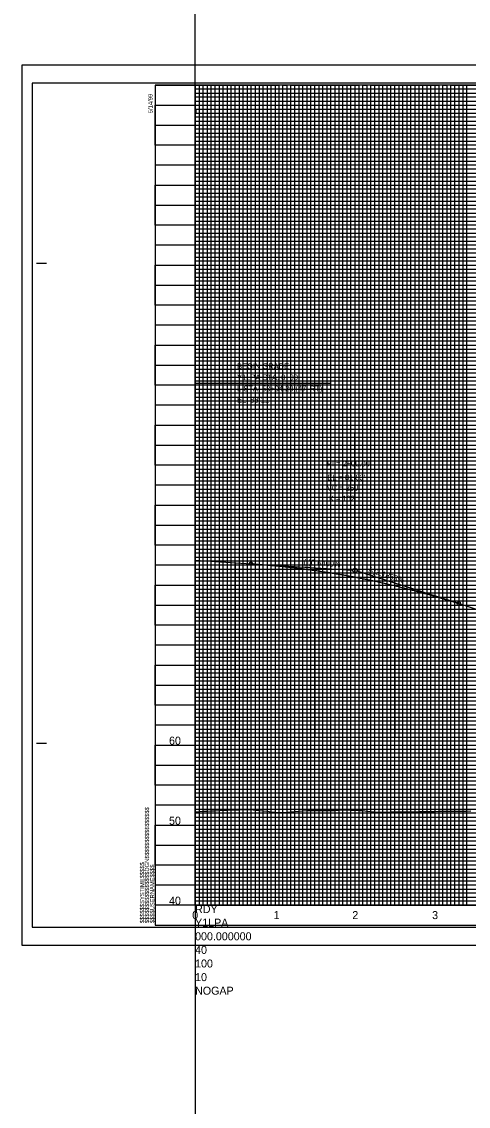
# Model space of a CAD drawing. Extents: x 2345490 to 2436403, y 465165 to 573888.
# Drawn here: x 2410678 to 2411237, y 518231 to 519587 of the extents above; entities that cross this region are included whole.
import ezdxf

# ---------------------------------------------------------------- set-up
doc = ezdxf.new("R2010")
doc.units = 0
for name, color, linetype in [('Old_Level_1', 7, 'Continuous'), ('Old_Level_18', 7, 'Continuous'), ('Old_Level_2', 7, 'Continuous'), ('Old_Level_40', 7, 'Continuous'), ('Old_Level_41', 7, 'Continuous'), ('Old_Level_42', 7, 'Continuous'), ('Old_Level_43', 7, 'Continuous'), ('Old_Level_50', 7, 'Continuous'), ('Old_Level_51', 7, 'Continuous'), ('Old_Level_52', 7, 'Continuous'), ('Old_Level_63', 7, 'Continuous')]:
    doc.layers.add(name, color=color, linetype=linetype)

msp = doc.modelspace()

# ---------------------------------------------------------------- linework, layer by layer
at = {"layer": 'Old_Level_1'}
msp.add_lwpolyline([(2410895.325, 518599.101), (2410900.325, 518599.36625), (2410905.325, 518599.6315), (2410910.325, 518599.897), (2410915.325, 518600.16275), (2410920.325, 518600.42875), (2410925.325, 518600.701), (2410930.325, 518600.896), (2410935.325, 518601.09075), (2410940.325, 518601.286), (2410945.325, 518601.4815), (2410950.325, 518601.677), (2410955.325, 518601.873), (2410960.325, 518602.069), (2410965.325, 518601.73975), (2410970.325, 518601.21325), (2410975.325, 518600.688), (2410980.325, 518600.164), (2410985.325, 518599.64175), (2410990.325, 518599.12075), (2410995.325, 518598.60025), (2411000.325, 518598.07125), (2411005.325, 518598.2125), (2411010.325, 518598.5945), (2411015.325, 518598.98175), (2411020.325, 518599.3745), (2411025.325, 518599.773), (2411030.325, 518600.1775), (2411035.325, 518600.58825), (2411040.325, 518600.65375), (2411045.325, 518600.54725), (2411050.325, 518600.59475), (2411055.325, 518600.6425), (2411060.325, 518600.69075), (2411065.325, 518600.73925), (2411070.325, 518600.78825), (2411075.325, 518601.0075), (2411080.325, 518601.3745), (2411085.325, 518601.44475), (2411090.325, 518601.18475), (2411095.325, 518600.93), (2411100.325, 518600.6805), (2411105.325, 518600.4365), (2411110.325, 518599.981), (2411115.325, 518599.5135), (2411120.325, 518599.05), (2411125.325, 518598.6505), (2411130.325, 518598.69575), (2411135.325, 518598.74275), (2411140.325, 518598.79175), (2411145.325, 518598.84275), (2411150.325, 518598.89575), (2411155.325, 518598.9505), (2411160.325, 518599.0075), (2411165.325, 518599.08675), (2411170.325, 518599.092), (2411175.325, 518599.186), (2411180.325, 518599.2755), (2411185.325, 518599.3645), (2411190.325, 518599.453), (2411195.325, 518599.54075), (2411200.325, 518599.628), (2411205.325, 518599.71475), (2411210.325, 518599.80075), (2411215.325, 518599.886), (2411220.325, 518599.8485), (2411225.325, 518599.77525), (2411230.325, 518599.77475), (2411235.325, 518599.83525), (2411240.325, 518600.069)], dxfattribs=at)
at = {"layer": 'Old_Level_18'}
msp.add_line((2410845.325, 518457.40475), (2410845.325, 518457.40475), dxfattribs=at)
msp.add_line((2410845.325, 518457.40475), (2410845.325, 518457.40475), dxfattribs=at)
msp.add_lwpolyline([(2412345.325, 519507.40475), (2410845.325, 519507.40475), (2410845.325, 518457.40475), (2412345.325, 518457.40475)], close=True, dxfattribs=at)
at = {"layer": 'Old_Level_2'}
for p, q in [((2410895.325, 519134.40475), (2410895.325, 518913.50475)), ((2411063.7915, 519134.40475), (2410895.325, 519134.40475)), ((2410895.325, 518913.50475), (2410965.325, 518909.02475)), ((2410965.325, 518909.02475), (2411092.58075, 518900.88075)), ((2411225.325, 518859.28375), (2411097.94525, 518899.87025)), ((2411225.325, 518859.28375), (2411745.325, 518693.59875))]:
    msp.add_line(p, q, dxfattribs=at)
for centre, radius in [((2410965.325, 518909.02475), 2.25), ((2411095.325, 518900.705), 2.75), ((2411225.325, 518859.28375), 2.25)]:
    msp.add_circle(centre, radius, dxfattribs=at)
msp.add_spline([(2410965.325, 518909.02475), (2410970.525, 518908.67875), (2410975.725, 518908.30625), (2410980.925, 518907.90725), (2410986.125, 518907.48175), (2410991.325, 518907.02975), (2410996.525, 518906.5515), (2411001.725, 518906.0465), (2411006.925, 518905.515), (2411012.125, 518904.95725), (2411017.325, 518904.37275), (2411022.525, 518903.762), (2411027.725, 518903.12475), (2411032.925, 518902.46075), (2411038.125, 518901.7705), (2411043.325, 518901.05375), (2411048.525, 518900.3105), (2411053.725, 518899.54075), (2411058.925, 518898.7445), (2411064.125, 518897.92175), (2411069.325, 518897.07275), (2411074.525, 518896.197), (2411079.725, 518895.29475), (2411084.925, 518894.36625), (2411090.125, 518893.41125), (2411095.325, 518892.4295), (2411100.525, 518891.4215), (2411105.725, 518890.387), (2411110.925, 518889.326), (2411116.125, 518888.2385), (2411121.325, 518887.1245), (2411126.525, 518885.984), (2411131.725, 518884.817), (2411136.925, 518883.6235), (2411142.125, 518882.40375), (2411147.325, 518881.15725), (2411152.525, 518879.8845), (2411157.725, 518878.585), (2411162.925, 518877.25925), (2411168.125, 518875.90675), (2411173.325, 518874.528), (2411178.525, 518873.12275), (2411183.725, 518871.691), (2411188.925, 518870.23275), (2411194.125, 518868.748), (2411199.325, 518867.23675), (2411204.525, 518865.69925), (2411209.725, 518864.135), (2411214.925, 518862.54425), (2411220.125, 518860.92725), (2411225.325, 518859.28375)], degree=3, dxfattribs=at)
at = {"layer": 'Old_Level_40'}
msp.add_line((2410845.325, 518457.40475), (2410845.325, 518457.40475), dxfattribs=at)
msp.add_line((2410845.325, 518457.40475), (2410845.325, 518457.40475), dxfattribs=at)
msp.add_line((2410845.325, 518457.40475), (2410845.325, 518457.40475), dxfattribs=at)
msp.add_line((2410845.325, 518457.40475), (2410845.325, 518457.40475), dxfattribs=at)
at = {"layer": 'Old_Level_41'}
for p, q in [((2410696.825, 519284.90475), (2410709.325, 519284.90475)), ((2410696.825, 518684.90475), (2410709.325, 518684.90475)), ((2412345.325, 518482.40475), (2410845.325, 518482.40475))]:
    msp.add_line(p, q, dxfattribs=at)
for points in [[(2410845.325, 519507.40475), (2410895.325, 519507.40475), (2410895.325, 518482.40475), (2410945.325, 518482.40475), (2410945.325, 519507.40475), (2410995.325, 519507.40475), (2410995.325, 518482.40475), (2411045.325, 518482.40475), (2411045.325, 519507.40475), (2411095.325, 519507.40475), (2411095.325, 518482.40475), (2411145.325, 518482.40475), (2411145.325, 519507.40475), (2411195.325, 519507.40475), (2411195.325, 518482.40475), (2411245.325, 518482.40475)], [(2410920.325, 518482.40475), (2410920.325, 519507.40475), (2410970.325, 519507.40475), (2410970.325, 518482.40475), (2411020.325, 518482.40475), (2411020.325, 519507.40475), (2411070.325, 519507.40475), (2411070.325, 518482.40475), (2411120.325, 518482.40475), (2411120.325, 519507.40475), (2411170.325, 519507.40475), (2411170.325, 518482.40475), (2411220.325, 518482.40475), (2411220.325, 519507.40475), (2411270.325, 519507.40475)], [(2410845.325, 519457.40475), (2412145.275, 519457.40475)], [(2412145.275, 519407.40475), (2410845.325, 519407.40475), (2410845.325, 519357.35475), (2412345.325, 519357.35475)], [(2412345.325, 519332.40475), (2410845.325, 519332.40475), (2410845.325, 519382.40475), (2412145.275, 519382.40475)], [(2412345.325, 519307.40475), (2410845.325, 519307.40475), (2410845.325, 519257.40475), (2412345.325, 519257.40475)], [(2412345.325, 519232.40475), (2410845.325, 519232.40475), (2410845.325, 519282.40475), (2412345.325, 519282.40475)], [(2412345.325, 519207.40475), (2410845.325, 519207.40475), (2410845.325, 519157.40475), (2412345.325, 519157.40475)], [(2412345.325, 519107.40475), (2410845.325, 519107.40475), (2410845.325, 519057.40475), (2412345.325, 519057.40475)], [(2412345.325, 519007.40475), (2410845.325, 519007.40475), (2410845.325, 518957.40475), (2412345.325, 518957.40475)], [(2412345.325, 518907.40475), (2410845.325, 518907.40475), (2410845.325, 518857.40475), (2412345.325, 518857.40475)], [(2412345.325, 518832.40475), (2410845.325, 518832.40475), (2410845.325, 518882.40475), (2412345.325, 518882.40475)], [(2412345.325, 518807.40475), (2410845.325, 518807.40475), (2410845.325, 518757.40475), (2412345.325, 518757.40475)], [(2412345.325, 518732.40475), (2410845.325, 518732.40475), (2410845.325, 518782.40475), (2412345.325, 518782.40475)], [(2412345.325, 518707.40475), (2410845.325, 518707.40475), (2410845.325, 518657.40475), (2412345.325, 518657.40475)], [(2412345.325, 518607.40475), (2410845.325, 518607.40475), (2410845.325, 518557.40475), (2412345.325, 518557.40475)], [(2412345.325, 518532.40475), (2410845.325, 518532.40475), (2410845.325, 518582.40475), (2412345.325, 518582.40475)], [(2412345.325, 518507.40475), (2410845.325, 518507.40475)], [(2410882.825, 518457.40475), (2410882.825, 518457.40475)]]:
    msp.add_lwpolyline(points, dxfattribs=at)
at = {"layer": 'Old_Level_42'}
for points in [[(2412145.275, 519432.40475), (2410845.425, 519432.40475), (2410845.425, 519482.35475), (2412145.275, 519482.35475)], [(2412345.325, 519132.40475), (2410845.325, 519132.40475), (2410845.325, 519182.40475), (2412345.325, 519182.40475)], [(2412345.325, 519032.40475), (2410845.325, 519032.40475), (2410845.325, 519082.40475), (2412345.325, 519082.40475)], [(2412345.325, 518932.40475), (2410845.325, 518932.40475), (2410845.325, 518982.40475), (2412345.325, 518982.40475)], [(2412345.325, 518632.40475), (2410845.325, 518632.40475), (2410845.325, 518682.40475), (2412345.325, 518682.40475)]]:
    msp.add_lwpolyline(points, dxfattribs=at)
at = {"layer": 'Old_Level_43'}
for p, q in [((2412295.325, 519327.40475), (2410895.325, 519327.40475)), ((2410895.325, 519327.40475), (2410895.325, 519322.40475)), ((2410895.325, 519322.40475), (2412295.325, 519322.40475)), ((2412295.325, 519302.40475), (2410895.325, 519302.40475))]:
    msp.add_line(p, q, dxfattribs=at)
for points in [[(2410900.325, 519507.40475), (2410905.325, 519507.40475), (2410910.325, 519507.40475), (2410915.325, 519507.40475), (2410925.325, 519507.40475), (2410892.275, 519507.40475), (2410897.275, 519507.40475), (2410855.325, 519507.40475), (2410860.325, 519507.40475), (2410865.325, 519507.40475), (2410875.325, 519507.40475), (2410880.325, 519507.40475), (2410885.325, 519507.40475), (2410890.325, 519507.40475), (2410900.325, 519507.40475), (2410900.325, 518482.40475), (2410905.325, 518482.40475), (2410905.325, 519507.40475), (2410910.325, 519507.40475), (2410910.325, 518482.40475), (2410915.325, 518482.40475), (2410915.325, 519507.40475), (2410925.325, 519507.40475), (2410925.325, 518482.40475), (2410930.325, 518482.40475), (2410930.325, 519507.40475), (2410935.325, 519507.40475), (2410935.325, 518482.40475), (2410940.325, 518482.40475), (2410940.325, 519507.40475), (2410950.325, 519507.40475), (2410950.325, 518482.40475), (2410955.325, 518482.40475), (2410955.325, 519507.40475), (2410960.325, 519507.40475), (2410960.325, 518482.40475), (2410965.325, 518482.40475), (2410965.325, 519507.40475), (2410975.325, 519507.40475), (2410975.325, 518482.40475), (2410980.325, 518482.40475), (2410980.325, 519507.40475), (2410985.325, 519507.40475), (2410985.325, 518482.40475), (2410990.325, 518482.40475), (2410990.325, 519507.40475), (2411000.325, 519507.40475), (2411000.325, 518482.40475), (2411005.325, 518482.40475), (2411005.325, 519507.40475), (2411010.325, 519507.40475), (2411010.325, 518482.40475), (2411015.325, 518482.40475), (2411015.325, 519507.40475), (2411025.325, 519507.40475), (2411025.325, 518482.40475), (2411030.325, 518482.40475), (2411030.325, 519507.40475), (2411035.325, 519507.40475), (2411035.325, 518482.40475), (2411040.325, 518482.40475), (2411040.325, 519507.40475), (2411050.325, 519507.40475), (2411050.325, 518482.40475), (2411055.325, 518482.40475), (2411055.325, 519507.40475), (2411060.325, 519507.40475), (2411060.325, 518482.40475)], [(2412145.275, 519502.40475), (2410895.325, 519502.40475), (2410895.325, 519497.40475), (2412145.275, 519497.40475)], [(2411060.325, 518482.40475), (2411065.325, 518482.40475), (2411065.325, 519507.40475), (2411075.325, 519507.40475), (2411075.325, 518482.40475), (2411080.325, 518482.40475), (2411080.325, 519507.40475), (2411085.325, 519507.40475), (2411085.325, 518482.40475), (2411090.325, 518482.40475), (2411090.325, 519507.40475), (2411100.325, 519507.40475), (2411100.325, 518482.40475), (2411105.325, 518482.40475), (2411105.325, 519507.40475), (2411105.325, 519507.40475), (2411110.325, 519507.40475), (2411110.325, 518482.40475), (2411115.325, 518482.40475), (2411115.325, 519507.40475), (2411125.325, 519507.40475), (2411125.325, 518482.40475), (2411130.325, 518482.40475), (2411130.325, 519507.40475), (2411135.325, 519507.40475), (2411135.325, 518482.40475), (2411140.325, 518482.40475), (2411140.325, 519507.40475), (2411150.325, 519507.40475), (2411150.325, 518482.40475), (2411155.325, 518482.40475), (2411155.325, 519507.40475), (2411160.325, 519507.40475), (2411160.325, 518482.40475), (2411165.325, 518482.40475), (2411165.325, 519507.40475), (2411175.325, 519507.40475), (2411175.325, 518482.40475), (2411180.325, 518482.40475), (2411180.325, 519507.40475), (2411185.325, 519507.40475), (2411185.325, 518482.40475), (2411190.325, 518482.40475), (2411190.325, 519507.40475), (2411200.325, 519507.40475), (2411200.325, 518482.40475), (2411205.325, 518482.40475), (2411205.325, 519507.40475), (2411210.325, 519507.40475), (2411210.325, 518482.40475), (2411215.325, 518482.40475), (2411215.325, 519507.40475), (2411225.325, 519507.40475), (2411225.325, 518482.40475), (2411240.325, 518482.40475)], [(2411230.325, 519507.40475), (2411230.325, 518482.40475), (2411235.325, 518482.40475), (2411235.325, 519507.40475)], [(2411230.325, 519506.80475), (2411230.325, 518482.40475), (2411235.325, 518482.40475), (2411235.325, 519506.80475)], [(2412145.275, 519492.40475), (2410895.325, 519492.40475), (2410895.325, 519487.40475), (2412145.275, 519487.40475)], [(2412145.275, 519476.65475), (2410896.325, 519476.65475), (2410896.325, 519472.40475), (2412145.275, 519472.40475)], [(2412145.275, 519467.40475), (2410895.325, 519467.40475), (2410895.325, 519462.40475), (2412145.275, 519462.40475)], [(2412145.275, 519452.40475), (2410895.325, 519452.40475), (2410895.325, 519447.40475), (2412145.275, 519447.40475)], [(2412145.275, 519442.40475), (2410895.325, 519442.40475), (2410895.325, 519437.40475), (2412145.275, 519437.40475)], [(2412145.275, 519427.40475), (2410895.325, 519427.40475), (2410895.325, 519422.40475), (2412145.275, 519422.40475)], [(2412145.275, 519417.40475), (2410895.325, 519417.40475), (2410895.325, 519412.40475), (2412145.275, 519412.40475)], [(2412145.275, 519402.40475), (2410895.325, 519402.40475), (2410895.325, 519397.40475), (2412145.275, 519397.40475)], [(2412145.275, 519392.40475), (2410895.325, 519392.40475), (2410895.325, 519387.40475), (2412145.275, 519387.40475)], [(2412145.275, 519377.40475), (2410895.325, 519377.40475), (2410895.325, 519372.40475), (2412145.275, 519372.40475)], [(2412295.325, 519367.40475), (2410895.325, 519367.40475), (2410895.325, 519367.40475), (2410895.325, 519347.40475), (2412295.325, 519347.40475)], [(2410895.325, 519362.40475), (2412295.325, 519362.40475)], [(2412295.325, 519352.40475), (2410895.325, 519352.40475)], [(2412295.325, 519342.40475), (2410895.325, 519342.40475), (2410895.325, 519337.40475), (2412295.325, 519337.40475)], [(2412295.325, 519317.40475), (2410895.325, 519317.40475), (2410895.325, 519312.40475), (2412295.325, 519312.40475)], [(2412295.325, 519297.40475), (2410895.325, 519297.40475), (2410895.325, 519292.40475), (2412295.325, 519292.40475)], [(2412295.325, 519287.40475), (2410895.325, 519287.40475)], [(2410895.325, 519277.40475), (2412295.325, 519277.40475)], [(2412295.325, 519272.40475), (2410895.325, 519272.40475), (2410895.325, 519267.40475), (2412295.325, 519267.40475)], [(2412295.325, 519262.40475), (2410895.325, 519262.40475), (2410895.325, 519252.40475), (2412295.325, 519252.40475)], [(2412295.325, 519247.40475), (2410895.325, 519247.40475), (2410895.325, 519242.40475), (2412295.325, 519242.40475)], [(2412295.325, 519237.40475), (2410895.325, 519237.40475), (2410895.325, 519227.40475), (2412295.325, 519227.40475)], [(2412295.325, 519222.40475), (2410895.325, 519222.40475), (2410895.325, 519217.40475), (2412295.325, 519217.40475)], [(2412295.325, 519212.40475), (2410895.325, 519212.40475), (2410895.325, 519202.40475), (2412295.325, 519202.40475)], [(2412295.325, 519197.40475), (2410895.325, 519197.40475), (2410895.325, 519192.40475), (2412295.325, 519192.40475)], [(2412295.325, 519187.40475), (2410895.325, 519187.40475), (2410895.325, 519177.40475), (2412295.325, 519177.40475)], [(2412295.325, 519172.40475), (2410895.325, 519172.40475), (2410895.325, 519167.40475), (2412295.325, 519167.40475)], [(2412295.325, 519162.40475), (2410895.325, 519162.40475), (2410895.325, 519152.40475), (2412295.325, 519152.40475)], [(2412295.325, 519147.40475), (2410895.325, 519147.40475), (2410895.325, 519142.40475), (2412295.325, 519142.40475)], [(2412295.325, 519137.40475), (2410895.325, 519137.40475), (2410895.325, 519127.40475), (2412295.325, 519127.40475)], [(2412295.325, 519122.40475), (2410895.325, 519122.40475), (2410895.325, 519117.40475), (2412295.325, 519117.40475)], [(2412295.325, 519112.40475), (2410895.325, 519112.40475), (2410895.325, 519102.40475), (2412295.325, 519102.40475)], [(2412295.325, 519097.40475), (2410895.325, 519097.40475), (2410895.325, 519092.40475), (2412295.325, 519092.40475)], [(2412295.325, 519087.40475), (2410895.325, 519087.40475), (2410895.325, 519077.40475), (2412295.325, 519077.40475)], [(2412295.325, 519072.40475), (2410895.325, 519072.40475), (2410895.325, 519067.40475), (2412295.325, 519067.40475)], [(2412295.325, 519062.40475), (2410895.325, 519062.40475), (2410895.325, 519052.40475), (2412295.325, 519052.40475)], [(2412295.325, 519047.40475), (2410895.325, 519047.40475), (2410895.325, 519042.40475), (2412295.325, 519042.40475)], [(2412295.325, 519037.40475), (2410895.325, 519037.40475), (2410895.325, 519027.40475), (2412295.325, 519027.40475)], [(2412295.325, 519022.40475), (2410895.325, 519022.40475), (2410895.325, 519017.40475), (2412295.325, 519017.40475)], [(2412295.325, 519012.40475), (2410895.325, 519012.40475), (2410895.325, 519002.40475), (2412295.325, 519002.40475)], [(2412295.325, 518997.40475), (2410895.325, 518997.40475), (2410895.325, 518992.40475), (2412295.325, 518992.40475)], [(2412295.325, 518987.40475), (2410895.325, 518987.40475)], [(2410895.325, 518977.40475), (2412295.325, 518977.40475)], [(2412295.325, 518972.40475), (2410895.325, 518972.40475), (2410895.325, 518967.40475), (2412295.325, 518967.40475)], [(2412295.325, 518962.40475), (2410895.325, 518962.40475), (2410895.325, 518952.40475), (2412295.325, 518952.40475)], [(2412295.325, 518947.40475), (2410895.325, 518947.40475), (2410895.325, 518942.40475), (2412295.325, 518942.40475)], [(2412295.325, 518937.40475), (2410895.325, 518937.40475), (2410895.325, 518927.40475), (2412295.325, 518927.40475)], [(2412295.325, 518922.40475), (2410895.325, 518922.40475), (2410895.325, 518917.40475), (2412295.325, 518917.40475)], [(2412295.325, 518912.40475), (2410895.325, 518912.40475), (2410895.325, 518902.40475), (2412295.325, 518902.40475)], [(2412295.325, 518897.40475), (2410895.325, 518897.40475), (2410895.325, 518892.40475), (2412295.325, 518892.40475)], [(2412295.325, 518887.40475), (2410895.325, 518887.40475), (2410895.325, 518877.40475), (2412295.325, 518877.40475)], [(2412295.325, 518872.40475), (2410895.325, 518872.40475), (2410895.325, 518867.40475), (2412295.325, 518867.40475)], [(2412295.325, 518862.40475), (2410895.325, 518862.40475), (2410895.325, 518852.40475), (2412295.325, 518852.40475)], [(2412295.325, 518847.40475), (2410895.325, 518847.40475), (2410895.325, 518842.40475), (2412295.325, 518842.40475)], [(2412295.325, 518837.40475), (2410895.325, 518837.40475), (2410895.325, 518827.40475), (2412295.325, 518827.40475)], [(2412295.325, 518822.40475), (2410895.325, 518822.40475), (2410895.325, 518817.40475), (2412295.325, 518817.40475)], [(2412295.325, 518812.40475), (2410895.325, 518812.40475), (2410895.325, 518802.40475), (2412295.325, 518802.40475)], [(2412295.325, 518797.40475), (2410895.325, 518797.40475), (2410895.325, 518792.40475), (2412295.325, 518792.40475)], [(2412295.325, 518787.40475), (2410895.325, 518787.40475), (2410895.325, 518777.40475), (2412295.325, 518777.40475)], [(2412295.325, 518772.40475), (2410895.325, 518772.40475), (2410895.325, 518767.40475), (2412295.325, 518767.40475)], [(2412295.325, 518762.40475), (2410895.325, 518762.40475), (2410895.325, 518752.40475), (2412295.325, 518752.40475)], [(2412295.325, 518747.40475), (2410895.325, 518747.40475), (2410895.325, 518742.40475), (2412295.325, 518742.40475)], [(2412295.325, 518737.40475), (2410895.325, 518737.40475), (2410895.325, 518727.40475), (2412295.325, 518727.40475)], [(2412295.325, 518722.40475), (2410895.325, 518722.40475), (2410895.325, 518717.40475), (2412295.325, 518717.40475)], [(2412295.325, 518712.40475), (2410895.325, 518712.40475), (2410895.325, 518702.40475), (2412295.325, 518702.40475)], [(2412295.325, 518697.40475), (2410895.325, 518697.40475), (2410895.325, 518692.40475), (2412295.325, 518692.40475)], [(2412295.325, 518687.40475), (2410895.325, 518687.40475)], [(2410895.325, 518677.40475), (2412295.325, 518677.40475)], [(2412295.325, 518672.40475), (2410895.325, 518672.40475), (2410895.325, 518667.40475), (2412295.325, 518667.40475)], [(2412295.325, 518662.40475), (2410895.325, 518662.40475)], [(2410895.325, 518652.40475), (2412295.325, 518652.40475)], [(2412295.325, 518647.40475), (2410895.325, 518647.40475), (2410895.325, 518642.40475), (2412295.325, 518642.40475)], [(2412295.325, 518637.40475), (2410895.325, 518637.40475), (2410895.325, 518627.40475), (2412295.325, 518627.40475)], [(2412295.325, 518622.40475), (2410895.325, 518622.40475), (2410895.325, 518617.40475), (2412295.325, 518617.40475)], [(2412295.325, 518612.40475), (2410895.325, 518612.40475), (2410895.325, 518602.40475), (2412295.325, 518602.40475)], [(2412295.325, 518597.40475), (2410895.325, 518597.40475), (2410895.325, 518592.40475), (2412295.325, 518592.40475)], [(2412295.325, 518587.40475), (2410895.325, 518587.40475), (2410895.325, 518577.40475), (2412295.325, 518577.40475)], [(2412295.325, 518572.40475), (2410895.325, 518572.40475), (2410895.325, 518567.40475), (2412295.325, 518567.40475)], [(2412295.325, 518562.40475), (2410895.325, 518562.40475), (2410895.325, 518552.40475), (2412295.325, 518552.40475)], [(2412295.325, 518547.40475), (2410895.325, 518547.40475), (2410895.325, 518542.40475), (2412295.325, 518542.40475)], [(2412295.325, 518537.40475), (2410895.325, 518537.40475), (2410895.325, 518527.40475), (2412295.325, 518527.40475)], [(2412295.325, 518522.40475), (2410895.325, 518522.40475), (2410895.325, 518517.40475), (2412295.325, 518517.40475)], [(2412295.325, 518512.40475), (2410895.325, 518512.40475), (2410895.325, 518502.40475), (2412295.325, 518502.40475)], [(2412295.325, 518497.40475), (2410895.325, 518497.40475), (2410895.325, 518492.40475), (2412295.325, 518492.40475)], [(2412295.325, 518487.40475), (2410895.325, 518487.40475)]]:
    msp.add_lwpolyline(points, dxfattribs=at)
at = {"layer": 'Old_Level_50'}
msp.add_line((2410678.325, 518432.40475), (2410678.325, 518432.40475), dxfattribs=at)
msp.add_lwpolyline([(2412357.825, 519509.95475), (2410691.325, 519509.95475), (2410691.325, 518454.85475), (2412357.825, 518454.85475)], close=True, dxfattribs=at)
at = {"layer": 'Old_Level_51'}
msp.add_lwpolyline([(2412362.325, 519532.40475), (2410678.325, 519532.40475), (2410678.325, 518432.40475), (2412362.325, 518432.40475)], close=True, dxfattribs=at)
at = {"layer": 'Old_Level_52'}
msp.add_line((2410691.325, 518454.85475), (2410691.325, 518454.85475), dxfattribs=at)
at = {"layer": 'Old_Level_63'}
for p, q in [((2410895.325, 518482.40475), (2410895.325, 520982.40475)), ((2411045.325, 518901.86475), (2411045.325, 519072.12475)), ((2411095.325, 518896.86475), (2411095.325, 519072.12475)), ((2411145.325, 518887.04475), (2411145.325, 519072.12475)), ((2410895.325, 518913.50475), (2410895.325, 518692.26325)), ((2410945.325, 518910.30475), (2410945.325, 518692.26325)), ((2410995.325, 518906.66475), (2410995.325, 518692.26325)), ((2411045.325, 518900.53475), (2411045.325, 518692.26325)), ((2411095.325, 518888.30475), (2411095.325, 518692.26325)), ((2411145.325, 518870.33475), (2411145.325, 518692.26325)), ((2410895.325, 518482.40475), (2412469.0995, 518482.40475)), ((2410895.325, 518482.40475), (2410895.325, 515982.40475))]:
    msp.add_line(p, q, dxfattribs=at)

# ---------------------------------------------------------------- texts
at = {"layer": 'Old_Level_1'}
for s, height, p in [('60', 10.000001, (2410862.7115, 518682.90475)), ('50', 10.000001, (2410862.7115, 518582.90475)), ('40', 10.000001, (2410862.7115, 518482.90475)), ('0', 10, (2410891.666, 518464.90475)), ('1', 10, (2410993.5055, 518464.90475)), ('2', 10, (2411092.054, 518464.90475)), ('3', 10, (2411191.88875, 518464.90475))]:
    msp.add_text(s, height=height, dxfattribs=at).set_placement(p)
at = {"layer": 'Old_Level_2'}
for s, height, p in [('BEGIN GRADE', 7.0000005, (2410947.8335, 519152.548)), ('Y1LPA STA. 0+00', 7.0000005, (2410947.8335, 519138.548)), ("L STA. 53+04.20 (47' RT)", 7.0000005, (2410947.8335, 519124.548)), ('EL. 83.11', 7.000001, (2410947.8335, 519110.548)), ('PI = 2+00.00', 7.0000005, (2411060.325, 519030.705)), ("EL = 81.83'", 7.0000005, (2411060.79425, 519013.52)), ("VC = 260'", 7.000001, (2411060.22, 519000.497)), ('K = 102', 7.000001, (2411062.782, 518987.0695))]:
    msp.add_text(s, height=height, dxfattribs=at).set_placement(p)
for s, rotation, p in [('(-)0.6400%', 356.33806389, (2411030.9055, 518907.83425)), ('(-)3.1863%', 342.32681944, (2411111.614, 518898.664))]:
    msp.add_text(s, height=7.000001, rotation=rotation, dxfattribs=at).set_placement(p)
at = {"layer": 'Old_Level_41'}
for s, p in [('5/14/99', (2410842.075, 519472.20475)), ('$$$$$$$$$$$$$$$$DGN$$$$$$$$$$$$$$$$', (2410837.675, 518459.76725)), ('$$$$$$SYSTIME$$$$$', (2410831.625, 518459.76725)), ('$$$$USERNAME$$$$', (2410844.25, 518459.77975))]:
    msp.add_text(s, height=5.25, rotation=90, dxfattribs=at).set_placement(p)
at = {"layer": 'Old_Level_63'}
for s, p in [('RDY', (2410895.325, 518472.40475)), ('Y1LPA', (2410895.325, 518455.40475)), ('000.000000', (2410895.325, 518438.40475)), ('40', (2410895.325, 518421.40475)), ('100', (2410895.325, 518404.40475)), ('10', (2410895.325, 518387.40475)), ('NOGAP', (2410895.325, 518370.40475))]:
    msp.add_text(s, height=10.000001, dxfattribs=at).set_placement(p)

doc.saveas('drawing.dxf')
